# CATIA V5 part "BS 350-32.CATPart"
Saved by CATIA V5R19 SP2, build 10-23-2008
Part number: BS 300-32
Bounding box of the stored display mesh (mm): x -15.868 to 15.868, y -15.868 to 15.868, z 0 to 94
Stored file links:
  C:\Users\Bora\Desktop\3D Katı model\BS serisi\BS 300\BS 300-32.CATPart
  C:\Program Files\Dassault Systemes\B19\intel_a\reffiles\standard\MetricThickPitch.txt
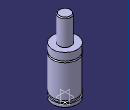
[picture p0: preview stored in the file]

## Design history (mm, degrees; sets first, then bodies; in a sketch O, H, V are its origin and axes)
Body1 (main body)
  Sketch1 on yz-plane, origin (0, 0, 0), H (0, 1, 0), V (0, 0, 1)
    point P1 (8, 93)
    point P3 (8, 93)
    point P5 (16, 51.5)
    point P6 (16, 49.5)
    point P9 (16, 51.5)
    point P14 (16, 49.5)
    line L1 (8, 93) -> (8, 61)
    arc A1 centre (7, 93) radius 1 from (8, 93) to (7, 94) ccw
    arc A2 centre (16, 50.5) radius 1 from (16, 51.5) to (16, 49.5) ccw
    line L2 (16, 0) -> (16, 4)
    line L3 (16, 51.5) -> (16, 61)
    line L4 (14.5, 7.5) -> (14.5, 4)
    line L5 (16, 7.5) -> (16, 49.5)
    line L6 (7, 94) -> (0, 94)
    point P15 (0, 94)
    line L7 (8, 61) -> (16, 61)
    line L8 (0, 0) -> (16, 0)
    line L9 (14.5, 7.5) -> (16, 7.5)
    line L10 (14.5, 4) -> (16, 4)
    coincidence: P15 V, P1 P3, P5 P9, P6 P14
    tangency: L6 A1
    horizontal: L7 H, L8 H, L9 H, L10 H
  Shaft1: profile Sketch1, axis Sketch1.V, angle 360
  Sketch2 on face of Shaft1 from Sketch1.L8, origin (0, 0, 0), H (1, 0, 0), V (0, -1, 0)
    point P1 (0, 0)
  Hole1: placed by Sketch2, at (0, 0, 0) direction (0, 0, 1), diameter 6.647, depth 4, threaded "M8", thread diameter 8, thread depth 4, pitch 1.25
